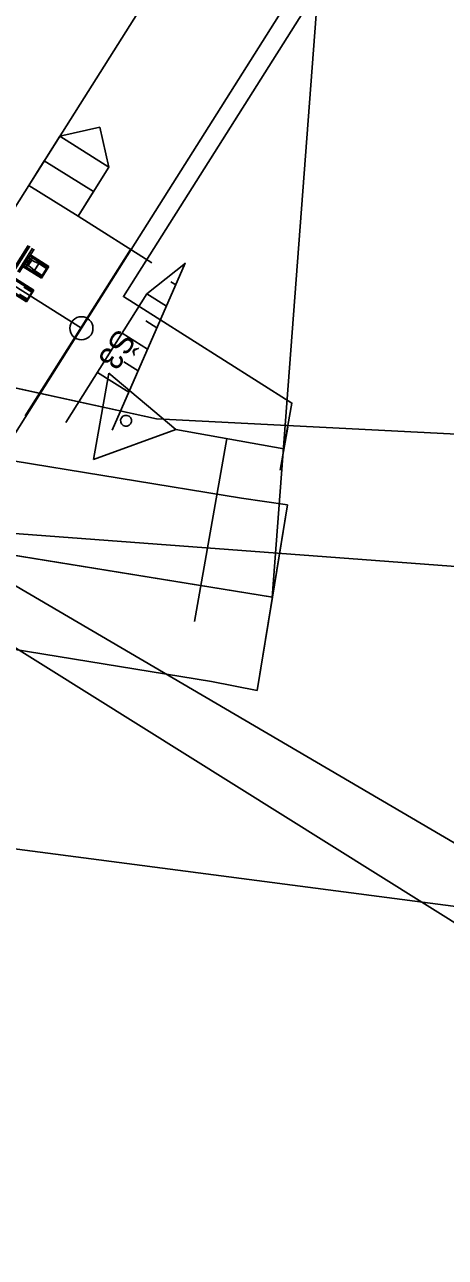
# Model space of a CAD drawing. Extents: x -746176 to -739709, y -1128407 to -1124482.
# Drawn here: x -743169.62 to -743160.56, y -1127113.64 to -1127087.08 of the extents above; entities that cross this region are included whole.
import ezdxf

# ---------------------------------------------------------------- set-up
doc = ezdxf.new("R2010")
doc.units = 0
for name, color, linetype in [('_Zabezpečovací zařízení', 7, 'Continuous'), ('_Zabezpečovací zařízení_trasa', 7, 'Continuous'), ('bublina_fialová_čára_tenká', 7, 'Continuous'), ('Hranice parcel', 7, 'Continuous'), ('KOL_ROST', 7, 'Continuous'), ('KOMUNIKACE_KRAJNICE', 7, 'Continuous'), ('OSA', 7, 'Continuous'), ('OSA_KOMUNIKACE', 7, 'Continuous'), ('SMER_VYS_VYROVNANI', 7, 'Continuous'), ('SRAFA_UPRAVA', 7, 'Continuous'), ('SVAH', 7, 'Continuous'), ('TRATIVOD', 7, 'Continuous'), ('Vrstva 53', 7, 'Continuous')]:
    doc.layers.add(name, color=color, linetype=linetype)

msp = doc.modelspace()

# ---------------------------------------------------------------- linework, layer by layer
at = {"layer": '_Zabezpečovací zařízení'}
for p, q in [((-743168.004, -1127089.286), (-743168.865, -1127089.483)), ((-743167.807, -1127090.147), (-743168.004, -1127089.286)), ((-743168.865, -1127089.483), (-743169.53, -1127090.542)), ((-743167.807, -1127090.147), (-743168.865, -1127089.483)), ((-743169.198, -1127090.012), (-743168.139, -1127090.677)), ((-743168.471, -1127091.206), (-743167.807, -1127090.147)), ((-743169.53, -1127090.542), (-743168.471, -1127091.206)), ((-743168.139, -1127096.449), (-743167.81, -1127094.588)), ((-743167.81, -1127094.588), (-743166.363, -1127095.804)), ((-743166.363, -1127095.804), (-743168.139, -1127096.449)), ((-743166.363, -1127095.804), (-743164.036, -1127096.216)), ((-743164.119, -1127096.681), (-743163.954, -1127095.75)), ((-743165.267, -1127095.997), (-743165.964, -1127099.936))]:
    msp.add_line(p, q, dxfattribs=at)
msp.add_lwpolyline([(-743168.471, -1127091.206), (-743168.139, -1127090.677), (-743169.198, -1127090.012), (-743169.53, -1127090.542), (-743168.471, -1127091.206)], dxfattribs=at)
for start, end in [(79.9608, 259.9608), (259.9608, 79.9608)]:
    msp.add_arc((-743167.437, -1127095.614), 0.118, start, end, dxfattribs=at)
at = {"layer": '_Zabezpečovací zařízení_trasa'}
for points in [[(-743164.036, -1127096.193), (-743163.862, -1127095.231), (-743167.492, -1127092.937), (-743158.53, -1127078.745)], [(-743168.471, -1127091.206), (-743166.88, -1127092.211)]]:
    msp.add_lwpolyline(points, dxfattribs=at)
at = {"layer": 'bublina_fialová_čára_tenká'}
for p, q in [((-743160.679, -1127051.634), (-743164.286, -1127099.423)), ((-743129.509, -1127122.8), (-743175.485, -1127095.847)), ((-743148.502, -1127099.644), (-743174.29, -1127097.707)), ((-743109.419, -1127138.306), (-743174.121, -1127097.814))]:
    msp.add_line(p, q, dxfattribs=at)
at = {"layer": 'Hranice parcel'}
msp.add_line((-743171.62, -1127104.6), (-743100.85, -1127113.88), dxfattribs=at)
msp.add_lwpolyline([(-743159.64, -1127094.74), (-743160.17, -1127095.91), (-743166.78, -1127095.57), (-743176.42, -1127093.47), (-743180.17, -1127093.19), (-743180.08, -1127092.14)], dxfattribs=at)
at = {"layer": 'KOL_ROST'}
for p, q in [((-743169.864, -1127092.342), (-743169.544, -1127091.834)), ((-743169.831, -1127092.362), (-743169.511, -1127091.855)), ((-743169.77, -1127092.401), (-743169.45, -1127091.894)), ((-743169.737, -1127092.422), (-743169.417, -1127091.914)), ((-743169.584, -1127092.257), (-743169.619, -1127092.235)), ((-743169.565, -1127092.149), (-743169.589, -1127092.186)), ((-743169.589, -1127092.186), (-743169.549, -1127092.211)), ((-743169.589, -1127092.186), (-743169.556, -1127092.213)), ((-743169.525, -1127092.173), (-743169.565, -1127092.149)), ((-743169.565, -1127092.149), (-743169.527, -1127092.167)), ((-743169.556, -1127092.213), (-743169.549, -1127092.211)), ((-743169.5, -1127092.124), (-743169.535, -1127092.101)), ((-743169.527, -1127092.167), (-743169.525, -1127092.173)), ((-743169.12, -1127092.318), (-743169.513, -1127092.067)), ((-743169.102, -1127092.29), (-743169.497, -1127092.041)), ((-743169.47, -1127092.152), (-743169.472, -1127092.135)), ((-743169.47, -1127092.152), (-743169.472, -1127092.135)), ((-743169.419, -1127092.185), (-743169.47, -1127092.153)), ((-743169.419, -1127092.185), (-743169.47, -1127092.153)), ((-743169.318, -1127092.228), (-743169.419, -1127092.185)), ((-743169.318, -1127092.228), (-743169.419, -1127092.185)), ((-743169.412, -1127092.376), (-743169.318, -1127092.228)), ((-743169.149, -1127092.335), (-743169.318, -1127092.228)), ((-743169.262, -1127092.544), (-743169.657, -1127092.295)), ((-743169.245, -1127092.516), (-743169.641, -1127092.269)), ((-743169.545, -1127092.271), (-743169.562, -1127092.277)), ((-743169.494, -1127092.304), (-743169.545, -1127092.271)), ((-743169.412, -1127092.376), (-743169.494, -1127092.304)), ((-743169.242, -1127092.483), (-743169.412, -1127092.376)), ((-743169.262, -1127092.544), (-743169.102, -1127092.29)), ((-743169.247, -1127092.52), (-743169.242, -1127092.483)), ((-743169.149, -1127092.335), (-743169.242, -1127092.483)), ((-743169.117, -1127092.314), (-743169.149, -1127092.335)), ((-743169.565, -1127093.023), (-743169.961, -1127092.777)), ((-743169.44, -1127092.825), (-743169.833, -1127092.574)), ((-743169.422, -1127092.798), (-743169.817, -1127092.549)), ((-743169.469, -1127092.842), (-743169.638, -1127092.735)), ((-743169.583, -1127093.051), (-743169.977, -1127092.802)), ((-743169.563, -1127092.99), (-743169.732, -1127092.883)), ((-743169.583, -1127093.051), (-743169.422, -1127092.798)), ((-743169.568, -1127093.028), (-743169.563, -1127092.99)), ((-743169.469, -1127092.842), (-743169.563, -1127092.99)), ((-743169.437, -1127092.821), (-743169.469, -1127092.842))]:
    msp.add_line(p, q, dxfattribs=at)
for points in [[(-743169.584, -1127092.257), (-743169.556, -1127092.213)], [(-743169.584, -1127092.257), (-743169.58, -1127092.261)], [(-743169.495, -1127092.125), (-743169.58, -1127092.261)], [(-743169.545, -1127092.271), (-743169.47, -1127092.152)], [(-743169.527, -1127092.167), (-743169.5, -1127092.124)], [(-743169.5, -1127092.124), (-743169.495, -1127092.125)], [(-743169.5, -1127092.124), (-743169.495, -1127092.125)]]:
    msp.add_lwpolyline(points, dxfattribs=at)
for radius in [0.0195, 0.0155, 0.0115]:
    msp.add_circle((-743169.555, -1127092.182), radius, dxfattribs=at)
for centre, start, end in [((-743169.486, -1127092.136), 2.1748, 130.3968), ((-743169.486, -1127092.136), 2.1748, 130.3968), ((-743169.567, -1127092.264), 165.0758, 293.2978)]:
    msp.add_arc(centre, 0.0137, start, end, dxfattribs=at)
at = {"layer": 'KOMUNIKACE_KRAJNICE'}
for p, q in [((-743164.95, -1127097.281), (-743171.211, -1127096.261)), ((-743164.95, -1127097.281), (-743163.96, -1127097.421)), ((-743164.612, -1127101.425), (-743163.96, -1127097.421)), ((-743165.593, -1127101.229), (-743173.53, -1127099.936)), ((-743165.593, -1127101.229), (-743164.612, -1127101.425))]:
    msp.add_line(p, q, dxfattribs=at)
at = {"layer": 'OSA'}
msp.add_lwpolyline([(-743169.53, -1127090.542), (-743178.712, -1127105.086)], dxfattribs=at)
at = {"layer": 'OSA_KOMUNIKACE'}
msp.add_line((-743164.284, -1127099.415), (-743182.5, -1127096.45), dxfattribs=at)
at = {"layer": 'SMER_VYS_VYROVNANI'}
msp.add_lwpolyline([(-743143.427, -1127049.192), (-743169.53, -1127090.542)], dxfattribs=at)
at = {"layer": 'SRAFA_UPRAVA'}
for p, q in [((-743164.95, -1127097.281), (-743171.211, -1127096.261)), ((-743163.96, -1127097.421), (-743164.95, -1127097.281)), ((-743164.284, -1127099.415), (-743163.96, -1127097.421)), ((-743172.37, -1127098.099), (-743164.284, -1127099.415)), ((-743164.284, -1127099.415), (-743172.37, -1127098.099)), ((-743164.612, -1127101.425), (-743164.284, -1127099.415)), ((-743173.53, -1127099.936), (-743165.593, -1127101.229)), ((-743165.593, -1127101.229), (-743164.612, -1127101.425))]:
    msp.add_line(p, q, dxfattribs=at)
at = {"layer": 'SVAH'}
for p, q in [((-743166.364, -1127092.684), (-743166.469, -1127092.618)), ((-743166.567, -1127093.147), (-743166.987, -1127092.882)), ((-743166.77, -1127093.61), (-743167.012, -1127093.458)), ((-743166.973, -1127094.073), (-743167.521, -1127093.728)), ((-743167.176, -1127094.536), (-743167.482, -1127094.344)), ((-743167.379, -1127095), (-743168.055, -1127094.573))]:
    msp.add_line(p, q, dxfattribs=at)
for points in [[(-743167.343, -1127091.922), (-743169.607, -1127095.509)], [(-743166.158, -1127092.217), (-743166.987, -1127092.882), (-743168.735, -1127095.651)], [(-743166.161, -1127092.221), (-743167.737, -1127095.814)]]:
    msp.add_lwpolyline(points, dxfattribs=at)
at = {"layer": 'TRATIVOD'}
for points in [[(-743175.637, -1127105.086), (-743168.399, -1127093.621), (-743157.384, -1127076.172), (-743151.775, -1127072.311)], [(-743172.796, -1127090.845), (-743168.399, -1127093.621)]]:
    msp.add_lwpolyline(points, dxfattribs=at)
msp.add_circle((-743168.399, -1127093.621), 0.25, dxfattribs=at)
at = {"layer": 'Vrstva 53'}
msp.add_lwpolyline([(-743032.8, -1126884.17), (-743063.8, -1126932.98), (-743082.27, -1126962.07), (-743093.1, -1126978.92), (-743136.47, -1127047.12), (-743147.78, -1127068.8), (-743159.64, -1127094.74), (-743160.17, -1127095.91), (-743166.78, -1127095.57), (-743176.42, -1127093.47), (-743180.17, -1127093.19), (-743180.08, -1127092.14), (-743178.51, -1127091.81), (-743175.35, -1127091.16), (-743150.075, -1127051.72), (-743124.8, -1127012.28), (-743108.67, -1126985.4), (-743080.97, -1126930.41), (-743079.79, -1126928.05), (-743048.51, -1126865.51), (-743045.12, -1126860.39), (-743029.24, -1126857.99)], dxfattribs=at)

# ---------------------------------------------------------------- texts
at = {"layer": 'TRATIVOD'}
msp.add_text('Š3', height=0.5, rotation=238, dxfattribs=at).set_placement((-743167.625, -1127093.603))

doc.saveas('drawing.dxf')
